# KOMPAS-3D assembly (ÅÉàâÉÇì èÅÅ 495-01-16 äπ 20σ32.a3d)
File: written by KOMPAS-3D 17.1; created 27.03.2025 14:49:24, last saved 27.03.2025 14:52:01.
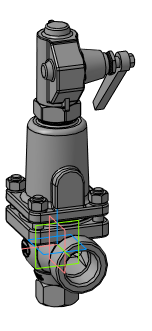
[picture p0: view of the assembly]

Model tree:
1. Поверхность без истории:1
2. Операция без истории:1  (labels: Капюшон DN 15x15, DN 20x20,@_DN 25x25, DN 20x32; ТДТА.КПП096.7762.00.03)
